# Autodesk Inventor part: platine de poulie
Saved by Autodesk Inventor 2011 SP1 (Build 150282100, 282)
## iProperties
Created: 2010-12
Part Number: platine de poulie
Document SubType Name: Modeling
Designer: eric
Density: 1 g/cm^3
Mass: 0.503959 g
Surface Area: 6.90754 cm^2
Volume: 0.503959 cm^3
Author: eric
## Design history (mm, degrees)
feature "Base1"
node "Solide1"
node "Corps solides"
node "Corps surfaciques"
